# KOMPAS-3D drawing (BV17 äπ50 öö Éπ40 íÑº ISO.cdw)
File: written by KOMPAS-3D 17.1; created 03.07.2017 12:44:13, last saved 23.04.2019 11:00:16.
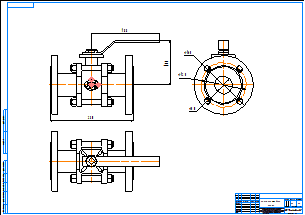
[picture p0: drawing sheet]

Sheet 1: A1, landscape

Title block, sheet 1: name: BV17 Ду50 ФФ Ру40 / без ISO; material: Внимание! Данный продукт является объектом авторского права ООО «Торговый Дом АДЛ». / Запрещается изменение, копирование, распространение / (в том числе путем копирования на другие сайты и ресурсы в Интернете) / или любое иное использование информации и объектов без предварительного / согласия правообладателя (ООО «Торговый Дом АДЛ»).; mass: 1,7; sheets: 1; organisation: ООО "Торговый дом АДЛ"; sheet format: A1; stored path: C:\Users\kka\KOMPAS_Work\!Trash\СС02 СС03 ФФ Смотровые стекла\СС01.cdw

Views: Спереди 1, Проекционный вид 2, Проекционный вид 3
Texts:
  Klimkovich
  ADL
Dimensions and other numbers on the sheet: 230; 188; 122; 125; 165; 50; 1:1; 1; 1,7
